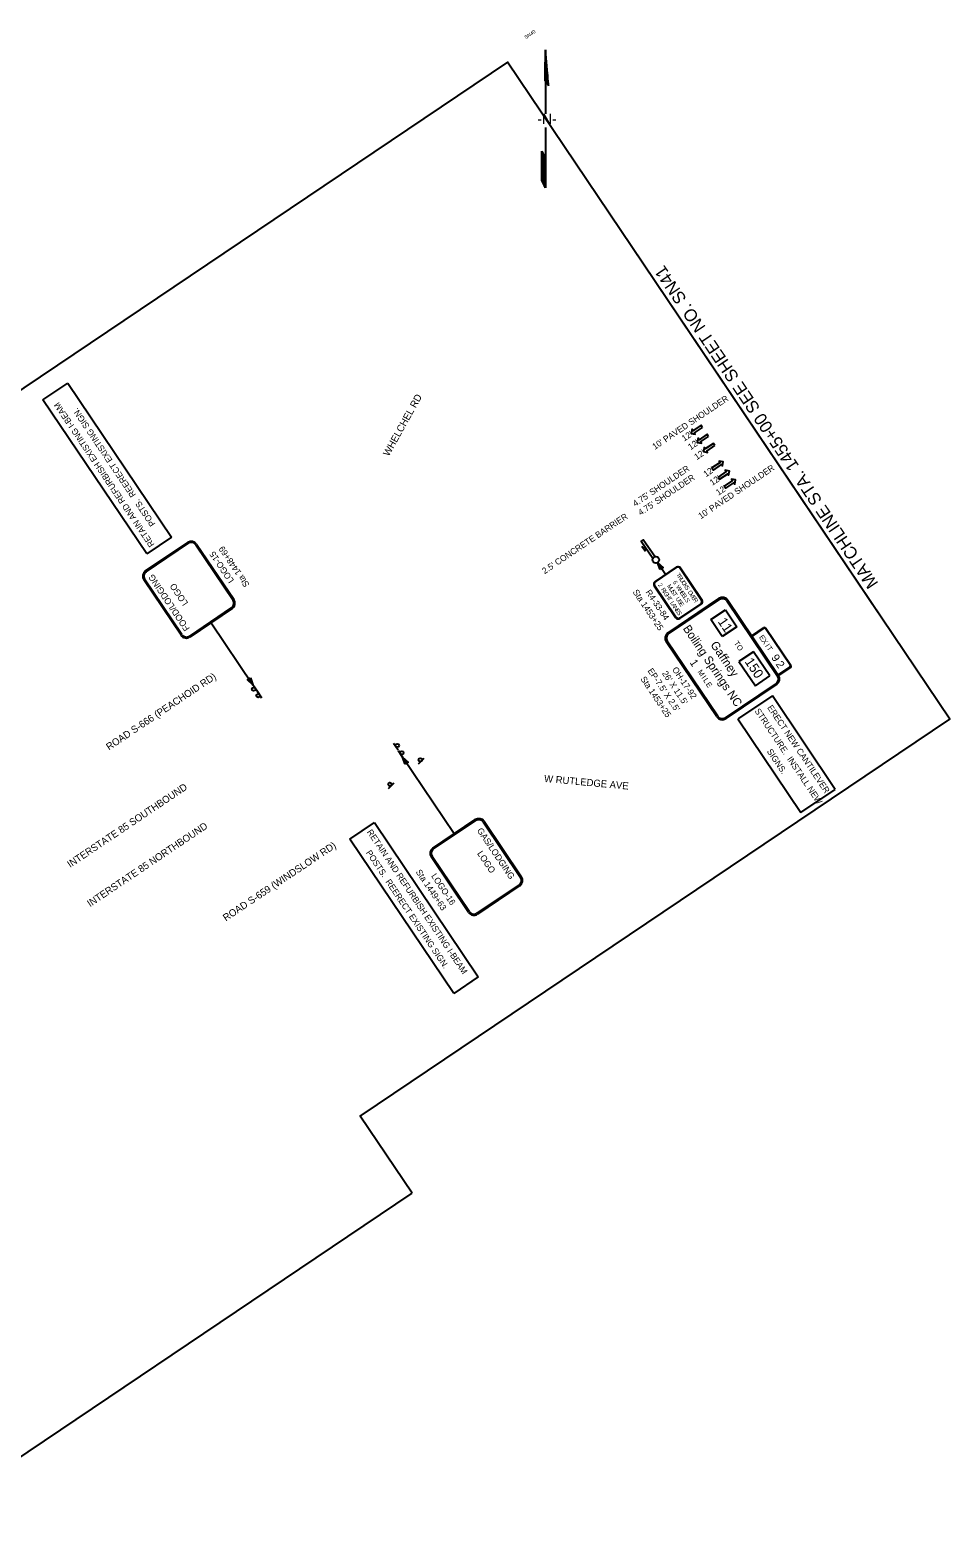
# Model space of a CAD drawing. Extents: x 1791953 to 1793697, y 1184916 to 1186619.
# Drawn here: x 1792658 to 1793697, y 1184916 to 1186619 of the extents above; entities that cross this region are included whole.
import ezdxf

# ---------------------------------------------------------------- set-up
doc = ezdxf.new("R2010")
doc.units = 0
for name, color, linetype in [('RD_DTM_BkLn1', 7, 'Continuous'), ('RD_DTM_BkLn2', 7, 'Continuous'), ('RD_EX_DR_Inlet_txCode', 7, 'Continuous'), ('RD_EX_Driveway', 7, 'Continuous'), ('RD_EX_Fence_ChLk', 7, 'Continuous'), ('RD_EX_H2O', 7, 'Continuous'), ('RD_EX_Road', 7, 'Continuous'), ('RD_EX_SU_Elec', 7, 'Continuous')]:
    doc.layers.add(name, color=color, linetype=linetype)

# ---------------------------------------------------------------- blocks, each defined once
blk = doc.blocks.new('NA5')
at = {"layer": 'RD_DTM_BkLn1'}
for p, q in [((47.5, 65.9), (26.8, 37.4)), ((26.8, 30.6), (47.5, 65.9)), ((27.2, 37.5), (14.5, 19.8)), ((28.1, 38.3), (26.8, 30.6)), ((14.5, 19.8), (5.5, 7.2)), ((-3.5, -5.3), (-18.5, -26.3)), ((-18.5, -26.3), (-43.3, -60.9)), ((-30.6, -36.2), (-22.3, -24.7)), ((-22.3, -24.7), (-24, -34)), ((-41.6, -51.6), (-30.6, -36.2)), ((-43.3, -60.9), (-41.6, -51.6))]:
    blk.add_line(p, q, dxfattribs=at)
for points in [[(27.1, 37.6), (39.2, 54.5)], [(27.4, 37.8), (47.4, 65.8)], [(27.6, 37.9), (46.9, 64.9)], [(27.6, 35.5), (39, 51.5)], [(27.7, 36.2), (40.6, 54.2)], [(27.7, 36), (40.1, 53.3)], [(27.7, 35.8), (39.6, 52.4)], [(27.8, 38.1), (46.4, 64)], [(27.8, 36.8), (42.2, 56.8)], [(27.8, 36.6), (41.7, 56)], [(27.8, 36.4), (41.1, 55.1)], [(27.9, 37.4), (43.8, 59.5)], [(27.9, 37.2), (43.2, 58.6)], [(27.9, 37), (42.7, 57.7)], [(28, 38.1), (45.3, 62.2)], [(28, 37.9), (44.8, 61.3)], [(28, 37.7), (44.3, 60.4)], [(28.1, 38.3), (45.8, 63.1)], [(26.9, 37.5), (29.9, 41.7)], [(27, 32), (30.1, 36.3)], [(27, 31.8), (29.6, 35.4)], [(27, 31.5), (29.1, 34.5)], [(27.1, 32.6), (31.7, 39)], [(27.1, 32.4), (31.2, 38.1)], [(27.1, 32.2), (30.6, 37.2)], [(27.2, 33.2), (33.3, 41.6)], [(27.2, 33), (32.7, 40.7)], [(27.2, 32.8), (32.2, 39.9)], [(27.3, 33.9), (34.8, 44.3)], [(27.3, 33.7), (34.3, 43.4)], [(27.3, 33.4), (33.8, 42.5)], [(27.4, 34.5), (36.4, 47)], [(27.4, 34.3), (35.9, 46.1)], [(27.4, 34.1), (35.4, 45.2)], [(27.5, 34.9), (37.5, 48.8)], [(27.5, 34.7), (36.9, 47.9)], [(27.6, 35.3), (38.5, 50.6)], [(27.6, 35.1), (38, 49.7)], [(26.8, 30.7), (27, 30.9)], [(26.9, 31.3), (28.5, 33.6)], [(26.9, 31.1), (28, 32.7)], [(26.9, 30.9), (27.5, 31.8)], [(-43.3, -60.8), (-24, -33.9)], [(-43.2, -60.1), (-23.9, -33.2)], [(-43.2, -60.3), (-23.9, -33.4)], [(-43.2, -60.5), (-24, -33.6)], [(-43.1, -59.7), (-23.8, -32.8)], [(-43.1, -59.9), (-23.9, -33)], [(-43, -59), (-23.7, -32.1)], [(-43, -59.2), (-23.7, -32.3)], [(-43, -59.4), (-23.8, -32.5)], [(-42.9, -58.6), (-23.6, -31.7)], [(-42.9, -58.8), (-23.7, -31.9)], [(-42.8, -58.1), (-23.5, -31.2)], [(-42.8, -58.3), (-23.6, -31.4)], [(-42.7, -57.5), (-23.4, -30.6)], [(-42.7, -57.7), (-23.5, -30.8)], [(-42.7, -57.9), (-23.5, -31)], [(-42.6, -57), (-23.3, -30.1)], [(-42.6, -57.2), (-23.4, -30.4)], [(-42.5, -56.4), (-23.2, -29.5)], [(-42.5, -56.6), (-23.2, -29.7)], [(-42.5, -56.8), (-23.3, -29.9)], [(-42.4, -55.9), (-23.1, -29)], [(-42.4, -56.1), (-23.2, -29.3)], [(-42.3, -55.3), (-23, -28.4)], [(-42.3, -55.5), (-23, -28.6)], [(-42.3, -55.7), (-23.1, -28.8)], [(-42.2, -54.8), (-22.9, -27.9)], [(-42.2, -55), (-23, -28.2)], [(-42.1, -54.4), (-22.8, -27.5)], [(-42.1, -54.6), (-22.9, -27.7)], [(-42, -53.7), (-22.7, -26.8)], [(-42, -53.9), (-22.7, -27.1)], [(-42, -54.2), (-22.8, -27.3)], [(-41.9, -53.3), (-22.6, -26.4)], [(-41.9, -53.5), (-22.7, -26.6)], [(-41.8, -52.6), (-22.5, -25.7)], [(-41.8, -52.8), (-22.5, -26)], [(-41.8, -53.1), (-22.6, -26.2)], [(-41.7, -52.2), (-22.4, -25.3)], [(-41.7, -52.4), (-22.5, -25.5)], [(-41.6, -51.7), (-22.3, -24.9)], [(-41.6, -52), (-22.4, -25.1)]]:
    blk.add_lwpolyline(points, dxfattribs=at)
blk.add_text('-N-', height=11.81, rotation=324.3865, dxfattribs=at).set_placement((-8.8, 3))
blk = doc.blocks.new('SARRW2')
at = {"layer": 'RD_EX_H2O'}
blk.add_lwpolyline([(-12, 1.2), (-12, -1.2), (-2.8, -1.2), (-2.8, -2.8), (0, 0), (-2.8, 2.8), (-2.8, 1.2)], close=True, dxfattribs=at)

msp = doc.modelspace()

# ---------------------------------------------------------------- linework, layer by layer
at = {"layer": 'RD_DTM_BkLn2'}
msp.add_lwpolyline([(1793616.1, 1185960.6), (1793476.5, 1186168), (1793336.9, 1186375.3)], dxfattribs=at)
at = {"layer": 'RD_EX_DR_Inlet_txCode'}
msp.add_lwpolyline([(1793089.7, 1185304.8), (1793031, 1185391.9), (1793697.1, 1185840.3), (1793197.3, 1186582.7), (1793197.3, 1186582.7), (1791953, 1185745.1), (1792511.4, 1184915.5)], close=True, dxfattribs=at)
at = {"layer": 'RD_EX_Fence_ChLk'}
for p, q in [((1792672.6, 1186201.3), (1792700.5, 1186220.1)), ((1792700.5, 1186220.1), (1792817.8, 1186045.9)), ((1792789.9, 1186027.1), (1792672.6, 1186201.3)), ((1792817.8, 1186045.9), (1792789.9, 1186027.1)), ((1793353.1, 1186029.8), (1793349.1, 1186035.5)), ((1793352.6, 1186035.3), (1793350.3, 1186033.7)), ((1793354.2, 1186033.1), (1793351.9, 1186031.5)), ((1793376, 1186004), (1793366.9, 1186017.4)), ((1793427.1, 1185952.9), (1793443.5, 1185963.8)), ((1792862.5, 1185949.3), (1792909.8, 1185879.1)), ((1793440, 1185933.7), (1793427.1, 1185952.9)), ((1793456.3, 1185944.7), (1793440, 1185933.7)), ((1792914.8, 1185871.7), (1792909.8, 1185879.1)), ((1792919.8, 1185864.3), (1792914.8, 1185871.8)), ((1793496.6, 1185866.9), (1793457.7, 1185840.7)), ((1793567.7, 1185761.1), (1793496.6, 1185866.9)), ((1793457.7, 1185840.7), (1793528.9, 1185735)), ((1793068.7, 1185813.2), (1793073.8, 1185805.7)), ((1793073.7, 1185804.9), (1793078.8, 1185797.4)), ((1793137, 1185710.8), (1793078.8, 1185797.4)), ((1793097, 1185789.9), (1793103.4, 1185796.3)), ((1793062.8, 1185762.1), (1793069.2, 1185768.5)), ((1793528.9, 1185735), (1793567.7, 1185761.1)), ((1793019.3, 1185704.7), (1793047.2, 1185723.5)), ((1793047.2, 1185723.5), (1793164.4, 1185549.2)), ((1793136.6, 1185530.5), (1793019.3, 1185704.7)), ((1793164.4, 1185549.2), (1793136.6, 1185530.5))]:
    msp.add_line(p, q, dxfattribs=at)
for points in [[(1792788.4, 1186007.9), (1792836.2, 1186040.1)], [(1792789, 1186006.9), (1792836.8, 1186039.1)], [(1792845.2, 1186037.4), (1792887.4, 1185974.7)], [(1792846.1, 1186038.1), (1792888.4, 1185975.4)], [(1793363.8, 1186024), (1793350.7, 1186043.1), (1793348.4, 1186041.5), (1793361.6, 1186022.3)], [(1792828.6, 1185935.2), (1792786.4, 1185997.9)], [(1792829.6, 1185935.9), (1792787.4, 1185998.6)], [(1793388, 1186012.1), (1793364.1, 1185996)], [(1793364.4, 1185995.5), (1793388.3, 1186011.6)], [(1793392.5, 1186010.8), (1793416.6, 1185974.9)], [(1793417.1, 1185975.3), (1793393, 1186011.1)], [(1793363.1, 1185991), (1793387.2, 1185955.2)], [(1793387.7, 1185955.5), (1793363.6, 1185991.3)], [(1792885.7, 1185966.4), (1792838, 1185934.2)], [(1792886.4, 1185965.4), (1792838.6, 1185933.2)], [(1793378.7, 1185937.9), (1793436.3, 1185976.6)], [(1793379.4, 1185936.9), (1793437, 1185975.6)], [(1793415.8, 1185970.8), (1793391.9, 1185954.7)], [(1793392.2, 1185954.2), (1793416.1, 1185970.3)], [(1793443.5, 1185963.8), (1793456.3, 1185944.7)], [(1793445.3, 1185974), (1793502.4, 1185889.1)], [(1793446.3, 1185974.7), (1793503.4, 1185889.8)], [(1793487, 1185943.1), (1793473.6, 1185934.1), (1793473.3, 1185934.6), (1793486.7, 1185943.6)], [(1793516.9, 1185901), (1793488.7, 1185942.8)], [(1793489.2, 1185943.1), (1793517.4, 1185901.3)], [(1793433.9, 1185843), (1793376.8, 1185927.9)], [(1793434.9, 1185843.7), (1793377.8, 1185928.5)], [(1793475.3, 1185916.6), (1793458.9, 1185905.6)], [(1793493.7, 1185889.2), (1793475.3, 1185916.6)], [(1793458.9, 1185905.6), (1793477.4, 1185878.2)], [(1793503.1, 1185890.3), (1793516.5, 1185899.3)], [(1793516.9, 1185898.8), (1793503.4, 1185889.8), (1793503.1, 1185890.3)], [(1793500.8, 1185880.8), (1793443.2, 1185842)], [(1793501.5, 1185879.8), (1793443.9, 1185841)], [(1793477.4, 1185878.2), (1793493.7, 1185889.2)], [(1793113.1, 1185694.7), (1793160.9, 1185726.9)], [(1793113.8, 1185693.8), (1793161.6, 1185725.9)], [(1793170.9, 1185725), (1793213.1, 1185662.2)], [(1793169.9, 1185724.3), (1793212.1, 1185661.6)], [(1793153.4, 1185622), (1793111.2, 1185684.8)], [(1793154.4, 1185622.7), (1793112.2, 1185685.4)], [(1793210.5, 1185653.2), (1793162.7, 1185621.1)], [(1793211.2, 1185652.3), (1793163.4, 1185620.1)]]:
    msp.add_lwpolyline(points, dxfattribs=at)
for points in [[(1793369.9, 1186009.5), (1793367, 1186017.4), (1793373.3, 1186011.8)], [(1792906.9, 1185887.1), (1792909.8, 1185879.1), (1792903.5, 1185884.8)], [(1793081.6, 1185789.5), (1793078.8, 1185797.4), (1793085, 1185791.7)]]:
    msp.add_lwpolyline(points, close=True, dxfattribs=at)
for centre, radius in [((1793364.9, 1186020.5), 3.71), ((1792910.6, 1185874.3), 2), ((1792915.6, 1185866.9), 2), ((1793072.9, 1185810.6), 2), ((1793077.9, 1185802.3), 2), ((1793098.8, 1185794.5), 2), ((1793064.6, 1185766.7), 2)]:
    msp.add_circle(centre, radius, dxfattribs=at)
for centre, radius, start, end in [((1792840.2, 1186034.1), 7.2, 33.9476, 123.9476), ((1792840.2, 1186034.1), 6, 33.9476, 123.9476), ((1792792.4, 1186001.9), 7.2, 123.9476, 213.9476), ((1792792.4, 1186001.9), 6, 123.9476, 213.9476), ((1793390, 1186009.1), 3.6, 33.9476, 123.9476), ((1793390, 1186009.1), 3, 33.9476, 123.9476), ((1793366.1, 1185993), 3.6, 123.9476, 213.9476), ((1793366.1, 1185993), 3, 123.9476, 213.9476), ((1792882.4, 1185971.4), 6, 303.9476, 33.9476), ((1792882.4, 1185971.4), 7.2, 303.9476, 33.9476), ((1793414.1, 1185973.2), 3, 303.9476, 33.9476), ((1793414.1, 1185973.2), 3.6, 303.9476, 33.9476), ((1793440.3, 1185970.6), 7.2, 33.9476, 123.9476), ((1793440.3, 1185970.6), 6, 33.9476, 123.9476), ((1793390.2, 1185957.2), 3.6, 213.9476, 303.9476), ((1793390.2, 1185957.2), 3, 213.9476, 303.9476), ((1792834.6, 1185939.2), 7.2, 213.9476, 303.9476), ((1792834.6, 1185939.2), 6, 213.9476, 303.9476), ((1793382.7, 1185931.9), 7.2, 123.9476, 213.9476), ((1793382.7, 1185931.9), 6, 123.9476, 213.9476), ((1793487.7, 1185942.1), 1.8, 33.9476, 123.9476), ((1793487.7, 1185942.1), 1.2, 33.9476, 123.9476), ((1793515.9, 1185900.3), 1.2, 303.9476, 33.9476), ((1793515.9, 1185900.3), 1.8, 303.9476, 33.9476), ((1793497.5, 1185885.8), 6, 303.9476, 33.9476), ((1793497.5, 1185885.8), 7.2, 303.9476, 33.9476), ((1793439.9, 1185847), 7.2, 213.9476, 303.9476), ((1793439.9, 1185847), 6, 213.9476, 303.9476), ((1793165, 1185720.9), 7.2, 33.9476, 123.9476), ((1793165, 1185720.9), 6, 33.9476, 123.9476), ((1793117.2, 1185688.8), 7.2, 123.9476, 213.9476), ((1793117.2, 1185688.8), 6, 123.9476, 213.9476), ((1793207.2, 1185658.2), 6, 303.9476, 33.9476), ((1793207.2, 1185658.2), 7.2, 303.9476, 33.9476), ((1793159.4, 1185626.1), 6, 213.9476, 303.9476), ((1793159.4, 1185626.1), 7.2, 213.9476, 303.9476)]:
    msp.add_arc(centre, radius, start, end, dxfattribs=at)

# ---------------------------------------------------------------- block references
at = {"layer": 'RD_DTM_BkLn2', "rotation": 35.61349782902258}
msp.add_blockref('NA5', (1793239.9, 1186515.3), dxfattribs=at)
at = {"layer": 'RD_EX_H2O', "xscale": 1.1999999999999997}
for p, yscale, rotation in [((1793404.9, 1186163.2), 1.2000000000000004, -146.05256015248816), ((1793411.8, 1186153), 1.2000000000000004, -146.05256015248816), ((1793418.8, 1186142.6), 1.2000000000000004, -146.05256015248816), ((1793441.1, 1186131.1), 1.2, 33.94743984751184), ((1793448.1, 1186120.7), 1.2, 33.94743984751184), ((1793455, 1186110.6), 1.2, 33.94743984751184)]:
    msp.add_blockref('SARRW2', p, dxfattribs=dict(at, yscale=yscale, rotation=rotation))

# ---------------------------------------------------------------- texts
at = {"layer": 'RD_DTM_BkLn2'}
msp.add_text('MATCHLINE STA. 1455+00 SEE SHEET NO. SN41', height=14, rotation=123.9476, dxfattribs=at).set_placement((1793616.7, 1185993.8))
at = {"layer": 'RD_EX_Driveway'}
for s, p in [("10' PAVED SHOULDER", (1793363.9, 1186144.5)), ("12'", (1793397.1, 1186153.9)), ("12'", (1793404.2, 1186144.2)), ("12'", (1793411.2, 1186132.9)), ("4.75' SHOULDER", (1793341.8, 1186080.2)), ("4.75' SHOULDER", (1793347.8, 1186070.1)), ("10' PAVED SHOULDER", (1793415.8, 1186066.1)), ("12'", (1793421.6, 1186113.6)), ("12'", (1793428.8, 1186103.9)), ("12'", (1793435.7, 1186092.7)), ("2.5' CONCRETE BARRIER", (1793239.3, 1186004))]:
    msp.add_text(s, height=7, rotation=33.9474, dxfattribs=at).set_placement(p)
at = {"layer": 'RD_EX_Fence_ChLk'}
for s, height, rotation, p in [('RETAIN AND REFURBISH EXISTING I-BEAM', 7, 123.9477, (1792798.9, 1186037.7)), ('POSTS.  REERECT EXISTING SIGN.', 7, 123.9477, (1792800, 1186061.1)), ('Sta 1448+69', 7, 123.9477, (1792906.2, 1185992.4)), ('LOGO-15', 7, 123.9477, (1792888.7, 1185997.1)), ('FOOD/LODGING', 7.2, 123.9476, (1792838.8, 1185942.9)), ('T', 4.8, 303.9476, (1793387.6, 1186003.6)), ('R', 4.8, 303.9476, (1793389.3, 1186000.9)), ('U', 4.8, 303.9476, (1793391.4, 1185997.9)), ('LOGO', 7.2, 123.9476, (1792836.9, 1185971.6)), ('Sta 1453+25', 7, 303.9477, (1793338.5, 1185984)), ('R4-33-84', 7, 303.9477, (1793353, 1185983.8)), ('2', 4.8, 303.9476, (1793367.1, 1185992.1)), ('R', 4.8, 303.9476, (1793370.5, 1185986.9)), ('I', 4.8, 303.9476, (1793372.6, 1185983.9)), ('G', 4.8, 303.9476, (1793373.5, 1185982.5)), ('H', 4.8, 303.9476, (1793375.5, 1185979.5)), ('M', 4.8, 303.9476, (1793377.4, 1185990.7)), ('U', 4.8, 303.9476, (1793379.7, 1185987.3)), ('S', 4.8, 303.9476, (1793381.7, 1185984.3)), ('6', 4.8, 303.9476, (1793383.9, 1185995)), ('T', 4.8, 303.9476, (1793383.6, 1185981.5)), ('W', 4.8, 303.9476, (1793387.4, 1185989.8)), ('H', 4.8, 303.9476, (1793389.9, 1185986.1)), ('E', 4.8, 303.9476, (1793391.9, 1185983.1)), ('E', 4.8, 303.9476, (1793393.7, 1185980.5)), ('C', 4.8, 303.9476, (1793393.4, 1185994.9)), ('K', 4.8, 303.9476, (1793395.3, 1185992)), ('S', 4.8, 303.9476, (1793397.2, 1185989.2)), ('O', 4.8, 303.9476, (1793400.7, 1185984)), ('V', 4.8, 303.9476, (1793402.7, 1185981)), ('T', 4.8, 303.9476, (1793377.5, 1185976.6)), ('L', 4.8, 303.9476, (1793380.8, 1185971.7)), ('A', 4.8, 303.9476, (1793382.3, 1185969.4)), ('N', 4.8, 303.9476, (1793384.4, 1185966.3)), ('E', 4.8, 303.9476, (1793386.5, 1185963.3)), ('U', 4.8, 303.9476, (1793387, 1185976.5)), ('S', 4.8, 303.9476, (1793389, 1185973.5)), ('E', 4.8, 303.9476, (1793391, 1185970.5)), ('L', 4.8, 303.9476, (1793395.5, 1185977.8)), ('S', 4.8, 303.9476, (1793397.3, 1185975.1)), ('E', 4.8, 303.9476, (1793404.8, 1185977.9)), ('R', 4.8, 303.9476, (1793406.6, 1185975.3)), ('S', 4.8, 303.9476, (1793388.3, 1185960.6)), ('Boiling Springs NC', 9.6, 303.9476, (1793395.1, 1185942.8)), ('11', 10.8, 303.9476, (1793434.5, 1185950.6)), ('TO', 6, 303.9476, (1793452.8, 1185926.3)), ('E', 6, 303.9476, (1793481.2, 1185933)), ('X', 6, 303.9476, (1793484.1, 1185928.7)), ('Gaffney', 9.6, 303.9476, (1793426.2, 1185924.5)), ('I', 6, 303.9476, (1793487.9, 1185923.1)), ('T', 6, 303.9476, (1793489.6, 1185920.6)), ('9', 9, 303.9476, (1793494.9, 1185909.9)), ("EP-7.5' X 2.5'", 7, 303.9477, (1793355.3, 1185895.1)), ('OH-17-92', 7, 303.9477, (1793383, 1185896.5)), ('1', 9, 303.9476, (1793402.8, 1185904.3)), ('M', 6, 303.9476, (1793411.7, 1185893.8)), ('150', 10.8, 303.9476, (1793464.9, 1185905.3)), ('2', 9, 303.9476, (1793500, 1185902.4)), ('Sta 1453+25', 7, 303.9477, (1793347.2, 1185885.8)), ("26' X 11.5'", 7, 303.9477, (1793371.6, 1185892)), ('I', 6, 303.9476, (1793416.1, 1185887.2)), ('L', 6, 303.9476, (1793418.1, 1185884.3)), ('E', 6, 303.9476, (1793421.1, 1185879.8)), ('STRUCTURE.  INSTALL NEW', 7, 303.9477, (1793476.2, 1185849.6)), ('ERECT NEW CANTILEVER', 7, 303.9477, (1793490.5, 1185853.4)), ('SIGNS.', 7, 303.9477, (1793490, 1185804)), ('RETAIN AND REFURBISH EXISTING I-BEAM', 7, 303.9477, (1793038.2, 1185712.9)), ('GAS/LODGING', 7.2, 303.9476, (1793162.5, 1185714.6)), ('POSTS.  REERECT EXISTING SIGN.', 7, 303.9477, (1793037.1, 1185689.5)), ('LOGO', 7.2, 303.9476, (1793162.7, 1185688.6)), ('Sta 1449+63', 7, 303.9477, (1793093.4, 1185667.7)), ('LOGO-16', 7, 303.9477, (1793110.8, 1185663.2))]:
    msp.add_text(s, height=height, rotation=rotation, dxfattribs=at).set_placement(p)
at = {"layer": 'RD_EX_Road'}
msp.add_text('SN40', height=4, rotation=33.9476, dxfattribs=at).set_placement((1793218.1, 1186608.4))
at = {"layer": 'RD_EX_SU_Elec'}
for s, rotation, p in [('WHELCHEL RD', 60.959, (1793063.3, 1186136.7)), ('ROAD S-666 (PEACHOID RD)', 33.8393, (1792747.2, 1185804.9)), ('W RUTLEDGE AVE', 354.7909, (1793238.5, 1185769.5)), ('INTERSTATE 85 SOUTHBOUND', 33.9476, (1792703.3, 1185672.2)), ('INTERSTATE 85 NORTHBOUND', 33.9476, (1792725.8, 1185627.9)), ('ROAD S-659 (WINDSLOW RD)', 33.8066, (1792879.2, 1185611.8))]:
    msp.add_text(s, height=8, rotation=rotation, dxfattribs=at).set_placement(p)

doc.saveas('drawing.dxf')
